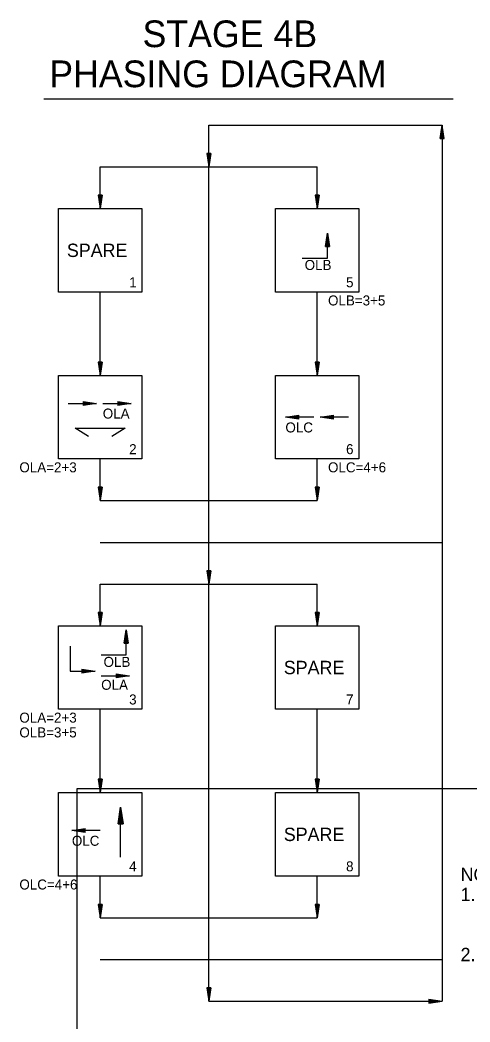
# Model space of a CAD drawing. Extents: x -218554 to 420030, y -565899 to -483460.
# Drawn here: x 418889.3 to 419024.1, y -565580.9 to -565280.7 of the extents above; entities that cross this region are included whole.
import ezdxf

# ---------------------------------------------------------------- set-up
doc = ezdxf.new("R2010")
doc.units = 0
for name, color, linetype in [('R_Draft', 7, 'Continuous'), ('T_Drafting', 7, 'Continuous'), ('T_Notes', 7, 'Continuous'), ('Template', 7, 'Continuous')]:
    doc.layers.add(name, color=color, linetype=linetype)

msp = doc.modelspace()

# ---------------------------------------------------------------- linework, layer by layer
at = {"layer": 'R_Draft'}
for p, q in [((419015.23, -565316.18), (419015.83, -565312.18)), ((419015.33, -565316.18), (419015.83, -565312.85)), ((419015.43, -565316.18), (419015.83, -565313.54)), ((419016.43, -565316.18), (419015.83, -565312.18)), ((419016.33, -565316.18), (419015.83, -565312.85)), ((419016.23, -565316.18), (419015.83, -565313.54)), ((419015.23, -565316.18), (419016.43, -565316.18)), ((419015.53, -565316.18), (419015.83, -565314.2)), ((419015.64, -565316.18), (419015.83, -565314.88)), ((419015.74, -565316.18), (419015.83, -565315.55)), ((419016.13, -565316.18), (419015.83, -565314.2)), ((419016.03, -565316.18), (419015.83, -565314.88)), ((419015.92, -565316.18), (419015.83, -565315.55)), ((418945.23, -565320.68), (418945.83, -565324.68)), ((418946.43, -565320.68), (418945.23, -565320.68)), ((418945.33, -565320.68), (418945.83, -565324.01)), ((418945.43, -565320.68), (418945.83, -565323.32)), ((418945.53, -565320.68), (418945.83, -565322.66)), ((418945.63, -565320.68), (418945.83, -565321.98)), ((418945.74, -565320.68), (418945.83, -565321.31)), ((418946.43, -565320.68), (418945.83, -565324.68)), ((418946.02, -565320.68), (418945.83, -565321.98)), ((418946.23, -565320.68), (418945.83, -565323.32)), ((418946.33, -565320.68), (418945.83, -565324.01)), ((418946.13, -565320.68), (418945.83, -565322.66)), ((418945.92, -565320.68), (418945.83, -565321.31)), ((418912.73, -565333.18), (418913.33, -565337.18)), ((418913.93, -565333.18), (418912.73, -565333.18)), ((418912.83, -565333.18), (418913.33, -565336.51)), ((418912.93, -565333.18), (418913.33, -565335.82)), ((418913.03, -565333.18), (418913.33, -565335.16)), ((418913.13, -565333.18), (418913.33, -565334.48)), ((418913.24, -565333.18), (418913.33, -565333.81)), ((418913.93, -565333.18), (418913.33, -565337.18)), ((418913.52, -565333.18), (418913.33, -565334.48)), ((418913.73, -565333.18), (418913.33, -565335.82)), ((418913.83, -565333.18), (418913.33, -565336.51)), ((418913.63, -565333.18), (418913.33, -565335.16)), ((418913.42, -565333.18), (418913.33, -565333.81)), ((418977.73, -565333.18), (418978.33, -565337.18)), ((418978.93, -565333.18), (418977.73, -565333.18)), ((418977.83, -565333.18), (418978.33, -565336.51)), ((418977.93, -565333.18), (418978.33, -565335.82)), ((418978.03, -565333.18), (418978.33, -565335.16)), ((418978.13, -565333.18), (418978.33, -565334.48)), ((418978.24, -565333.18), (418978.33, -565333.81)), ((418978.93, -565333.18), (418978.33, -565337.18)), ((418978.52, -565333.18), (418978.33, -565334.48)), ((418978.73, -565333.18), (418978.33, -565335.82)), ((418978.83, -565333.18), (418978.33, -565336.51)), ((418978.63, -565333.18), (418978.33, -565335.16)), ((418978.42, -565333.18), (418978.33, -565333.81)), ((418912.73, -565383.18), (418913.33, -565387.18)), ((418913.93, -565383.18), (418912.73, -565383.18)), ((418912.83, -565383.18), (418913.33, -565386.51)), ((418912.93, -565383.18), (418913.33, -565385.82)), ((418913.03, -565383.18), (418913.33, -565385.16)), ((418913.13, -565383.18), (418913.33, -565384.48)), ((418913.24, -565383.18), (418913.33, -565383.81)), ((418913.93, -565383.18), (418913.33, -565387.18)), ((418913.52, -565383.18), (418913.33, -565384.48)), ((418913.73, -565383.18), (418913.33, -565385.82)), ((418913.83, -565383.18), (418913.33, -565386.51)), ((418913.63, -565383.18), (418913.33, -565385.16)), ((418913.42, -565383.18), (418913.33, -565383.81)), ((418977.73, -565383.18), (418978.33, -565387.18)), ((418978.93, -565383.18), (418977.73, -565383.18)), ((418977.83, -565383.18), (418978.33, -565386.51)), ((418977.93, -565383.18), (418978.33, -565385.82)), ((418978.03, -565383.18), (418978.33, -565385.16)), ((418978.13, -565383.18), (418978.33, -565384.48)), ((418978.24, -565383.18), (418978.33, -565383.81)), ((418978.93, -565383.18), (418978.33, -565387.18)), ((418978.52, -565383.18), (418978.33, -565384.48)), ((418978.73, -565383.18), (418978.33, -565385.82)), ((418978.83, -565383.18), (418978.33, -565386.51)), ((418978.63, -565383.18), (418978.33, -565385.16)), ((418978.42, -565383.18), (418978.33, -565383.81)), ((418912.73, -565420.68), (418913.33, -565424.68)), ((418913.93, -565420.68), (418912.73, -565420.68)), ((418912.83, -565420.68), (418913.33, -565424.01)), ((418912.93, -565420.68), (418913.33, -565423.32)), ((418913.03, -565420.68), (418913.33, -565422.66)), ((418913.13, -565420.68), (418913.33, -565421.98)), ((418913.24, -565420.68), (418913.33, -565421.31)), ((418913.93, -565420.68), (418913.33, -565424.68)), ((418913.52, -565420.68), (418913.33, -565421.98)), ((418913.73, -565420.68), (418913.33, -565423.32)), ((418913.83, -565420.68), (418913.33, -565424.01)), ((418913.63, -565420.68), (418913.33, -565422.66)), ((418913.42, -565420.68), (418913.33, -565421.31)), ((418977.73, -565420.68), (418978.33, -565424.68)), ((418978.93, -565420.68), (418977.73, -565420.68)), ((418977.83, -565420.68), (418978.33, -565424.01)), ((418977.93, -565420.68), (418978.33, -565423.32)), ((418978.03, -565420.68), (418978.33, -565422.66)), ((418978.13, -565420.68), (418978.33, -565421.98)), ((418978.24, -565420.68), (418978.33, -565421.31)), ((418978.93, -565420.68), (418978.33, -565424.68)), ((418978.52, -565420.68), (418978.33, -565421.98)), ((418978.73, -565420.68), (418978.33, -565423.32)), ((418978.83, -565420.68), (418978.33, -565424.01)), ((418978.63, -565420.68), (418978.33, -565422.66)), ((418978.42, -565420.68), (418978.33, -565421.31)), ((418945.23, -565445.68), (418945.83, -565449.68)), ((418946.43, -565445.68), (418945.23, -565445.68)), ((418945.33, -565445.68), (418945.83, -565449.01)), ((418945.43, -565445.68), (418945.83, -565448.32)), ((418945.53, -565445.68), (418945.83, -565447.66)), ((418945.63, -565445.68), (418945.83, -565446.98)), ((418945.74, -565445.68), (418945.83, -565446.31)), ((418946.43, -565445.68), (418945.83, -565449.68)), ((418946.02, -565445.68), (418945.83, -565446.98)), ((418946.23, -565445.68), (418945.83, -565448.32)), ((418946.33, -565445.68), (418945.83, -565449.01)), ((418946.13, -565445.68), (418945.83, -565447.66)), ((418945.92, -565445.68), (418945.83, -565446.31)), ((418912.73, -565458.18), (418913.33, -565462.18)), ((418913.93, -565458.18), (418912.73, -565458.18)), ((418912.83, -565458.18), (418913.33, -565461.51)), ((418912.93, -565458.18), (418913.33, -565460.82)), ((418913.03, -565458.18), (418913.33, -565460.16)), ((418913.13, -565458.18), (418913.33, -565459.48)), ((418913.24, -565458.18), (418913.33, -565458.81)), ((418913.93, -565458.18), (418913.33, -565462.18)), ((418913.52, -565458.18), (418913.33, -565459.48)), ((418913.73, -565458.18), (418913.33, -565460.82)), ((418913.83, -565458.18), (418913.33, -565461.51)), ((418913.63, -565458.18), (418913.33, -565460.16)), ((418913.42, -565458.18), (418913.33, -565458.81)), ((418977.73, -565458.18), (418978.33, -565462.18)), ((418978.93, -565458.18), (418977.73, -565458.18)), ((418977.83, -565458.18), (418978.33, -565461.51)), ((418977.93, -565458.18), (418978.33, -565460.82)), ((418978.03, -565458.18), (418978.33, -565460.16)), ((418978.13, -565458.18), (418978.33, -565459.48)), ((418978.24, -565458.18), (418978.33, -565458.81)), ((418978.93, -565458.18), (418978.33, -565462.18)), ((418978.52, -565458.18), (418978.33, -565459.48)), ((418978.73, -565458.18), (418978.33, -565460.82)), ((418978.83, -565458.18), (418978.33, -565461.51)), ((418978.63, -565458.18), (418978.33, -565460.16)), ((418978.42, -565458.18), (418978.33, -565458.81)), ((418912.73, -565508.18), (418913.33, -565512.18)), ((418913.93, -565508.18), (418912.73, -565508.18)), ((418912.83, -565508.18), (418913.33, -565511.51)), ((418912.93, -565508.18), (418913.33, -565510.82)), ((418913.03, -565508.18), (418913.33, -565510.16)), ((418913.13, -565508.18), (418913.33, -565509.48)), ((418913.24, -565508.18), (418913.33, -565508.81)), ((418913.93, -565508.18), (418913.33, -565512.18)), ((418913.52, -565508.18), (418913.33, -565509.48)), ((418913.73, -565508.18), (418913.33, -565510.82)), ((418913.83, -565508.18), (418913.33, -565511.51)), ((418913.63, -565508.18), (418913.33, -565510.16)), ((418913.42, -565508.18), (418913.33, -565508.81)), ((418977.73, -565508.18), (418978.33, -565512.18)), ((418978.93, -565508.18), (418977.73, -565508.18)), ((418977.83, -565508.18), (418978.33, -565511.51)), ((418977.93, -565508.18), (418978.33, -565510.82)), ((418978.03, -565508.18), (418978.33, -565510.16)), ((418978.13, -565508.18), (418978.33, -565509.48)), ((418978.24, -565508.18), (418978.33, -565508.81)), ((418978.93, -565508.18), (418978.33, -565512.18)), ((418978.52, -565508.18), (418978.33, -565509.48)), ((418978.73, -565508.18), (418978.33, -565510.82)), ((418978.83, -565508.18), (418978.33, -565511.51)), ((418978.63, -565508.18), (418978.33, -565510.16)), ((418978.42, -565508.18), (418978.33, -565508.81)), ((418912.73, -565545.68), (418913.33, -565549.68)), ((418913.93, -565545.68), (418912.73, -565545.68)), ((418912.83, -565545.68), (418913.33, -565549.01)), ((418912.93, -565545.68), (418913.33, -565548.32)), ((418913.03, -565545.68), (418913.33, -565547.66)), ((418913.13, -565545.68), (418913.33, -565546.98)), ((418913.24, -565545.68), (418913.33, -565546.31)), ((418913.93, -565545.68), (418913.33, -565549.68)), ((418913.52, -565545.68), (418913.33, -565546.98)), ((418913.73, -565545.68), (418913.33, -565548.32)), ((418913.83, -565545.68), (418913.33, -565549.01)), ((418913.63, -565545.68), (418913.33, -565547.66)), ((418913.42, -565545.68), (418913.33, -565546.31)), ((418977.73, -565545.68), (418978.33, -565549.68)), ((418978.93, -565545.68), (418977.73, -565545.68)), ((418977.83, -565545.68), (418978.33, -565549.01)), ((418977.93, -565545.68), (418978.33, -565548.32)), ((418978.03, -565545.68), (418978.33, -565547.66)), ((418978.13, -565545.68), (418978.33, -565546.98)), ((418978.24, -565545.68), (418978.33, -565546.31)), ((418978.93, -565545.68), (418978.33, -565549.68)), ((418978.52, -565545.68), (418978.33, -565546.98)), ((418978.73, -565545.68), (418978.33, -565548.32)), ((418978.83, -565545.68), (418978.33, -565549.01)), ((418978.63, -565545.68), (418978.33, -565547.66)), ((418978.42, -565545.68), (418978.33, -565546.31)), ((418945.23, -565570.68), (418945.83, -565574.68)), ((418946.43, -565570.68), (418945.23, -565570.68)), ((418945.33, -565570.68), (418945.83, -565574.01)), ((418945.43, -565570.68), (418945.83, -565573.32)), ((418945.53, -565570.68), (418945.83, -565572.66)), ((418945.63, -565570.68), (418945.83, -565571.98)), ((418945.74, -565570.68), (418945.83, -565571.31)), ((418946.43, -565570.68), (418945.83, -565574.68)), ((418946.02, -565570.68), (418945.83, -565571.98)), ((418946.23, -565570.68), (418945.83, -565573.32)), ((418946.33, -565570.68), (418945.83, -565574.01)), ((418946.13, -565570.68), (418945.83, -565572.66)), ((418945.92, -565570.68), (418945.83, -565571.31)), ((419011.83, -565574.08), (419015.83, -565574.68)), ((419011.83, -565574.08), (419011.83, -565575.28)), ((419011.83, -565574.18), (419015.16, -565574.68)), ((419011.83, -565574.28), (419014.47, -565574.68)), ((419011.83, -565574.38), (419013.81, -565574.68)), ((419011.83, -565574.49), (419013.13, -565574.68)), ((419011.83, -565574.59), (419012.46, -565574.68)), ((419011.83, -565575.28), (419015.83, -565574.68)), ((419011.83, -565574.88), (419013.13, -565574.68)), ((419011.83, -565575.08), (419014.47, -565574.68)), ((419011.83, -565575.18), (419015.16, -565574.68)), ((419011.83, -565574.98), (419013.81, -565574.68)), ((419011.83, -565574.77), (419012.46, -565574.68))]:
    msp.add_line(p, q, dxfattribs=at)
at = {"layer": 'T_Drafting'}
for p, q in [((418945.83, -565574.68), (418945.83, -565312.18)), ((418945.83, -565312.18), (419015.83, -565312.18)), ((419015.83, -565312.18), (419015.83, -565574.68)), ((418913.33, -565337.18), (418913.33, -565324.68)), ((418913.33, -565324.68), (418978.33, -565324.68)), ((418978.33, -565337.18), (418978.33, -565324.68)), ((418980.78, -565348.49), (418981.38, -565344.49)), ((418981.38, -565345.16), (418980.88, -565348.49)), ((418980.98, -565348.49), (418981.38, -565345.84)), ((418981.38, -565346.51), (418981.08, -565348.49)), ((418981.38, -565351.99), (418981.38, -565344.49)), ((418981.38, -565344.49), (418981.98, -565348.49)), ((418981.88, -565348.49), (418981.38, -565345.16)), ((418981.38, -565345.84), (418981.78, -565348.49)), ((418981.68, -565348.49), (418981.38, -565346.51)), ((418980.78, -565348.49), (418981.98, -565348.49)), ((418981.19, -565348.49), (418981.38, -565347.19)), ((418981.38, -565347.86), (418981.29, -565348.49)), ((418981.38, -565347.19), (418981.58, -565348.49)), ((418981.47, -565348.49), (418981.38, -565347.86)), ((418973.88, -565351.99), (418981.38, -565351.99)), ((418913.33, -565387.18), (418913.33, -565362.18)), ((418978.33, -565387.18), (418978.33, -565362.18)), ((418908.16, -565394.99), (418912.16, -565395.59)), ((418908.16, -565394.99), (418908.16, -565396.19)), ((418918.58, -565394.99), (418922.58, -565395.59)), ((418918.58, -565394.99), (418918.58, -565396.19)), ((418903.67, -565395.59), (418912.16, -565395.59)), ((418911.49, -565395.59), (418908.16, -565395.09)), ((418908.16, -565395.19), (418910.81, -565395.59)), ((418910.14, -565395.59), (418908.16, -565395.29)), ((418908.16, -565395.39), (418909.46, -565395.59)), ((418908.79, -565395.59), (418908.16, -565395.49)), ((418912.16, -565395.59), (418908.16, -565396.19)), ((418908.16, -565396.09), (418911.49, -565395.59)), ((418910.81, -565395.59), (418908.16, -565395.99)), ((418908.16, -565395.89), (418910.14, -565395.59)), ((418909.46, -565395.59), (418908.16, -565395.78)), ((418908.16, -565395.68), (418908.79, -565395.59)), ((418914.09, -565395.59), (418922.58, -565395.59)), ((418921.91, -565395.59), (418918.58, -565395.09)), ((418918.58, -565395.19), (418921.23, -565395.59)), ((418920.56, -565395.59), (418918.58, -565395.29)), ((418918.58, -565395.39), (418919.88, -565395.59)), ((418919.21, -565395.59), (418918.58, -565395.49)), ((418922.58, -565395.59), (418918.58, -565396.19)), ((418918.58, -565396.09), (418921.91, -565395.59)), ((418921.23, -565395.59), (418918.58, -565395.99)), ((418918.58, -565395.89), (418920.56, -565395.59)), ((418919.88, -565395.59), (418918.58, -565395.78)), ((418918.58, -565395.68), (418919.21, -565395.59)), ((418968.82, -565399.68), (418972.82, -565399.08)), ((418977.31, -565399.68), (418968.82, -565399.68)), ((418972.82, -565400.28), (418968.82, -565399.68)), ((418972.82, -565399.18), (418969.49, -565399.68)), ((418969.49, -565399.68), (418972.82, -565400.18)), ((418970.17, -565399.68), (418972.82, -565399.28)), ((418972.82, -565400.08), (418970.17, -565399.68)), ((418972.82, -565399.38), (418970.84, -565399.68)), ((418970.84, -565399.68), (418972.82, -565399.98)), ((418971.52, -565399.68), (418972.82, -565399.48)), ((418972.82, -565399.87), (418971.52, -565399.68)), ((418972.82, -565399.59), (418972.19, -565399.68)), ((418972.19, -565399.68), (418972.82, -565399.77)), ((418972.82, -565400.28), (418972.82, -565399.08)), ((418979.27, -565399.68), (418983.27, -565399.08)), ((418987.76, -565399.68), (418979.27, -565399.68)), ((418983.27, -565400.28), (418979.27, -565399.68)), ((418983.27, -565399.18), (418979.94, -565399.68)), ((418979.94, -565399.68), (418983.27, -565400.18)), ((418980.63, -565399.68), (418983.27, -565399.28)), ((418983.27, -565400.08), (418980.63, -565399.68)), ((418983.27, -565399.38), (418981.29, -565399.68)), ((418981.29, -565399.68), (418983.27, -565399.98)), ((418981.97, -565399.68), (418983.27, -565399.48)), ((418983.27, -565399.87), (418981.97, -565399.68)), ((418983.27, -565399.59), (418982.64, -565399.68)), ((418982.64, -565399.68), (418983.27, -565399.77)), ((418983.27, -565400.28), (418983.27, -565399.08)), ((418913.33, -565424.68), (418913.33, -565412.18)), ((418978.33, -565424.68), (418978.33, -565412.18)), ((418913.33, -565424.68), (418978.33, -565424.68)), ((418913.33, -565437.18), (419015.83, -565437.18)), ((418913.33, -565449.68), (418978.33, -565449.68)), ((418913.33, -565462.18), (418913.33, -565449.68)), ((418978.33, -565462.18), (418978.33, -565449.68)), ((418920.51, -565467.42), (418921.11, -565463.42)), ((418921.11, -565470.92), (418921.11, -565463.42)), ((418921.11, -565463.42), (418921.71, -565467.42)), ((418921.11, -565464.09), (418920.61, -565467.42)), ((418920.71, -565467.42), (418921.11, -565464.77)), ((418921.11, -565465.44), (418920.81, -565467.42)), ((418920.92, -565467.42), (418921.11, -565466.12)), ((418921.11, -565466.79), (418921.02, -565467.42)), ((418921.61, -565467.42), (418921.11, -565464.09)), ((418921.11, -565464.77), (418921.51, -565467.42)), ((418921.41, -565467.42), (418921.11, -565465.44)), ((418921.11, -565466.12), (418921.31, -565467.42)), ((418921.2, -565467.42), (418921.11, -565466.79)), ((418904.28, -565468.29), (418904.28, -565475.79)), ((418920.51, -565467.42), (418921.71, -565467.42)), ((418913.61, -565470.92), (418921.11, -565470.92)), ((418904.28, -565475.79), (418911.78, -565475.79)), ((418907.78, -565475.19), (418911.78, -565475.79)), ((418907.78, -565475.19), (418907.78, -565476.39)), ((418911.11, -565475.79), (418907.78, -565475.29)), ((418907.78, -565475.39), (418910.42, -565475.79)), ((418909.75, -565475.79), (418907.78, -565475.49)), ((418907.78, -565475.59), (418909.08, -565475.79)), ((418908.41, -565475.79), (418907.78, -565475.69)), ((418911.78, -565475.79), (418907.78, -565476.39)), ((418907.78, -565476.29), (418911.11, -565475.79)), ((418910.42, -565475.79), (418907.78, -565476.19)), ((418907.78, -565476.09), (418909.75, -565475.79)), ((418909.08, -565475.79), (418907.78, -565475.98)), ((418907.78, -565475.88), (418908.41, -565475.79)), ((418913.61, -565477.13), (418922.1, -565477.13)), ((418918.1, -565476.53), (418922.1, -565477.13)), ((418918.1, -565476.53), (418918.1, -565477.73)), ((418921.43, -565477.13), (418918.1, -565476.63)), ((418918.1, -565476.74), (418920.74, -565477.13)), ((418920.08, -565477.13), (418918.1, -565476.84)), ((418918.1, -565476.94), (418919.4, -565477.13)), ((418918.73, -565477.13), (418918.1, -565477.04)), ((418922.1, -565477.13), (418918.1, -565477.73)), ((418918.1, -565477.63), (418921.43, -565477.13)), ((418920.74, -565477.13), (418918.1, -565477.53)), ((418918.1, -565477.43), (418920.08, -565477.13)), ((418919.4, -565477.13), (418918.1, -565477.33)), ((418918.1, -565477.23), (418918.73, -565477.13)), ((418913.33, -565512.18), (418913.33, -565487.18)), ((418978.33, -565512.18), (418978.33, -565487.18)), ((418918.69, -565521.54), (418919.44, -565516.54)), ((418919.44, -565517.37), (418918.81, -565521.54)), ((418919.44, -565531.54), (418919.44, -565516.54)), ((418919.44, -565516.54), (418920.19, -565521.54)), ((418920.06, -565521.54), (418919.44, -565517.37)), ((418918.94, -565521.54), (418919.44, -565518.23)), ((418919.44, -565519.07), (418919.07, -565521.54)), ((418919.2, -565521.54), (418919.44, -565519.91)), ((418919.44, -565520.75), (418919.32, -565521.54)), ((418919.44, -565518.23), (418919.94, -565521.54)), ((418919.81, -565521.54), (418919.44, -565519.07)), ((418919.44, -565519.91), (418919.68, -565521.54)), ((418919.56, -565521.54), (418919.44, -565520.75)), ((418904.83, -565523.53), (418908.83, -565522.93)), ((418913.31, -565523.53), (418904.83, -565523.53)), ((418908.83, -565524.13), (418904.83, -565523.53)), ((418908.83, -565523.03), (418905.49, -565523.53)), ((418905.49, -565523.53), (418908.83, -565524.03)), ((418906.18, -565523.53), (418908.83, -565523.14)), ((418908.83, -565523.93), (418906.18, -565523.53)), ((418908.83, -565523.24), (418906.85, -565523.53)), ((418906.85, -565523.53), (418908.83, -565523.83)), ((418907.53, -565523.53), (418908.83, -565523.34)), ((418908.83, -565523.73), (418907.53, -565523.53)), ((418908.83, -565523.44), (418908.19, -565523.53)), ((418908.19, -565523.53), (418908.83, -565523.63)), ((418908.83, -565524.13), (418908.83, -565522.93)), ((418918.69, -565521.54), (418920.19, -565521.54)), ((418913.33, -565549.68), (418913.33, -565537.18)), ((418978.33, -565549.68), (418978.33, -565537.18)), ((418913.33, -565549.68), (418978.33, -565549.68)), ((418913.33, -565562.18), (419015.83, -565562.18)), ((418945.83, -565574.68), (419015.83, -565574.68))]:
    msp.add_line(p, q, dxfattribs=at)
for points in [[(418900.83, -565337.18), (418925.83, -565337.18), (418925.83, -565362.18), (418900.83, -565362.18)], [(418965.83, -565337.18), (418990.83, -565337.18), (418990.83, -565362.18), (418965.83, -565362.18)], [(418900.83, -565387.18), (418925.83, -565387.18), (418925.83, -565412.18), (418900.83, -565412.18)], [(418965.83, -565387.18), (418990.83, -565387.18), (418990.83, -565412.18), (418965.83, -565412.18)], [(418900.83, -565462.18), (418925.83, -565462.18), (418925.83, -565487.18), (418900.83, -565487.18)], [(418965.83, -565462.18), (418990.83, -565462.18), (418990.83, -565487.18), (418965.83, -565487.18)], [(418900.83, -565512.18), (418925.83, -565512.18), (418925.83, -565537.18), (418900.83, -565537.18)], [(418965.83, -565512.18), (418990.83, -565512.18), (418990.83, -565537.18), (418965.83, -565537.18)]]:
    msp.add_lwpolyline(points, close=True, dxfattribs=at)
msp.add_lwpolyline([(418909.83, -565405.48), (418905.83, -565402.98), (418920.83, -565402.98), (418916.83, -565405.48)], dxfattribs=at)
at = {"layer": 'T_Notes'}
msp.add_line((418896.46, -565304.27), (419019.1, -565304.27), dxfattribs=at)
at = {"layer": 'Template'}
msp.add_lwpolyline([(419214.2, -565511.02), (418906.32, -565511.02), (418906.32, -565641.34), (419214.2, -565641.34)], close=True, dxfattribs=at)

# ---------------------------------------------------------------- texts
at = {"layer": 'T_Drafting'}
for s, height, p in [('SPARE', 4, (418903.33, -565351.68)), ('OLB', 3, (418974.6, -565355.57)), ('OLB=3+5', 3, (418981.59, -565366.2)), ('OLA', 3, (418914.09, -565400.09)), ('OLC', 3, (418968.82, -565404.25)), ('OLA=2+3', 3, (418889.1, -565416.2)), ('OLC=4+6', 3, (418981.59, -565416.2)), ('OLB', 3, (418914.32, -565474.5)), ('SPARE', 4, (418968.33, -565476.68)), ('OLA', 3, (418913.61, -565481.36)), ('OLA=2+3', 3, (418889.1, -565491.2)), ('OLB=3+5', 3, (418889.1, -565495.63)), ('SPARE', 4, (418968.33, -565526.68)), ('OLC', 3, (418904.83, -565528.1)), ('OLC=4+6', 3, (418889.1, -565541.2))]:
    msp.add_text(s, height=height, dxfattribs=at).set_placement(p)
at = {"layer": 'T_Notes'}
for s, p in [('STAGE 4B', (418926, -565288.8)), ('PHASING DIAGRAM', (418898.05, -565300.8))]:
    msp.add_text(s, height=8, rotation=360, dxfattribs=at).set_placement(p)
for s, height, p in [('1', 3, (418921.99, -565360.76)), ('5', 3, (418986.99, -565360.76)), ('2', 3, (418921.99, -565410.76)), ('6', 3, (418986.99, -565410.76)), ('3', 3, (418921.99, -565485.76)), ('7', 3, (418986.99, -565485.76)), ('4', 3, (418921.99, -565535.76)), ('8', 3, (418986.99, -565535.76)), ('NOTES:', 4, (419021.31, -565538.68)), ('1. OVERLAPS A AND C TO HAVE A MINIMUM', 4, (419021.31, -565544.68)), ('2. PHASE OLB FYA SHALL BE TERMINATED', 4, (419021.31, -565562.68))]:
    msp.add_text(s, height=height, dxfattribs=at).set_placement(p)

doc.saveas('drawing.dxf')
